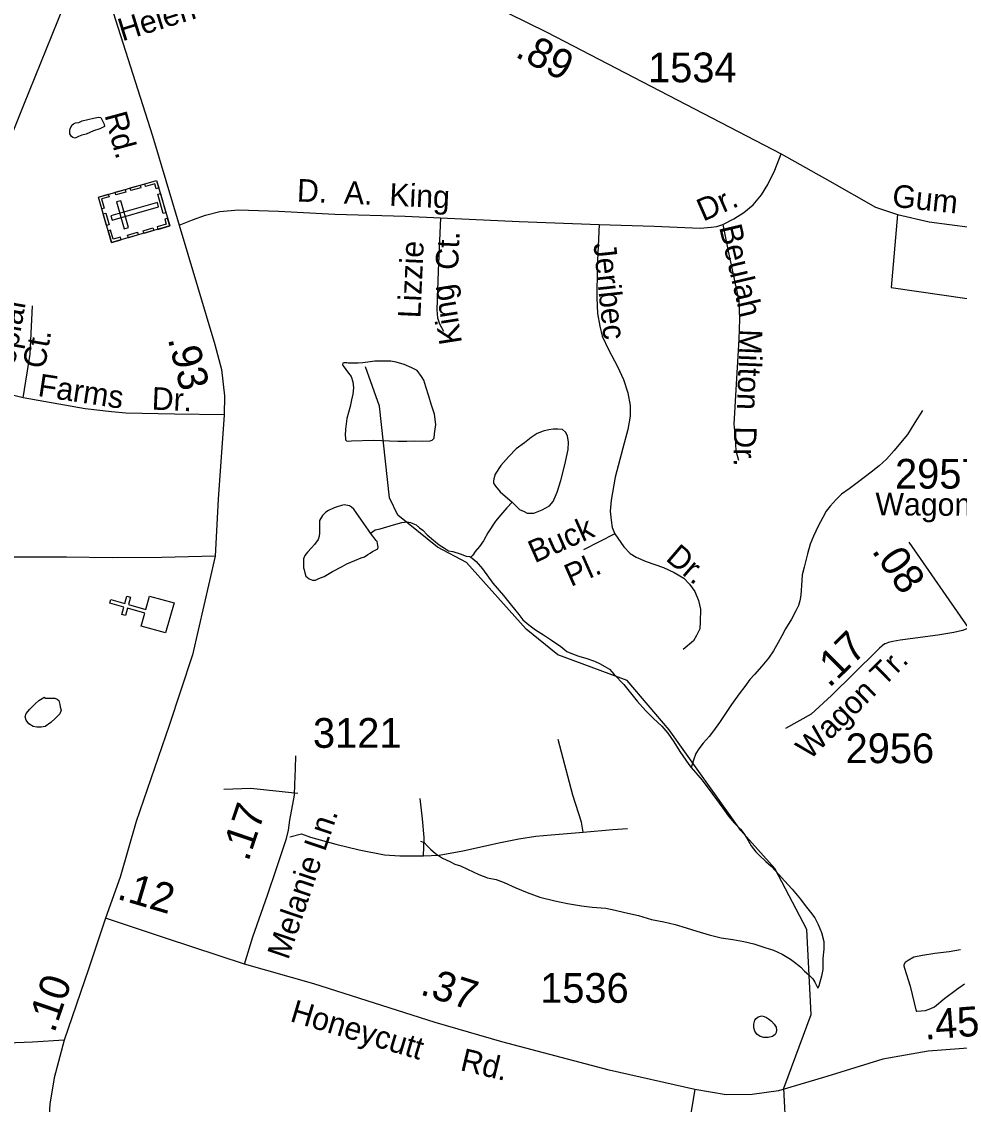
# Model space of a CAD drawing. Extents: x 2082433 to 2279600, y 546599 to 755198.
# Drawn here: x 2109763 to 2113702, y 651011 to 655560 of the extents above; entities that cross this region are included whole.
import ezdxf

# ---------------------------------------------------------------- set-up
doc = ezdxf.new("R2010")
doc.units = 0
for name, color, linetype in [('Exist Cultural Cemetery CELL', 7, 'Continuous'), ('Exist Cultural Church CELL', 7, 'Continuous'), ('Exist Hydrographic Misc Water Feature', 7, 'Continuous'), ('Exist Road Non-System Type 51', 7, 'Continuous'), ('Exist Road Non-System Type 51 Label', 7, 'Continuous'), ('Exist Road Secondary Mileage Hundredths English Label', 7, 'Continuous'), ('Exist Road Secondary Type 51 Attributed', 7, 'Continuous'), ('Exist Road Secondary Type 51 Label', 7, 'Continuous'), ('Exist Road Secondary Type 51 Number Label', 7, 'Continuous'), ('Exist Utilities Electrical Transmission Line', 7, 'Continuous')]:
    doc.layers.add(name, color=color, linetype=linetype)

msp = doc.modelspace()

# ---------------------------------------------------------------- linework, layer by layer
at = {"layer": 'Exist Cultural Cemetery CELL'}
for points in [[(2110140.2, 654631.6), (2110085.5, 654823), (2110330.3, 654893), (2110385, 654701.6)], [(2110264, 654862.2), (2110222.3, 654850.3), (2110219.2, 654861.2), (2110260.8, 654873.1)], [(2110339.4, 654861.1), (2110328.4, 654858), (2110322.3, 654879.1), (2110283.5, 654868), (2110280.4, 654878.7), (2110330.3, 654893)], [(2110127.2, 654835), (2110130.3, 654824), (2110099.3, 654815.2), (2110110.5, 654776.2), (2110099.8, 654773.1), (2110085.5, 654823)], [(2110200.6, 654844.1), (2110158.9, 654832.2), (2110155.8, 654843.1), (2110197.4, 654855)], [(2110358.2, 654753.6), (2110334.9, 654835.2), (2110345.8, 654838.4), (2110369.2, 654756.8)], [(2110138.4, 654744.4), (2110143.6, 654726.5), (2110338.5, 654782.2), (2110333.4, 654800.2)], [(2110194.4, 654689.5), (2110212.4, 654694.6), (2110180, 654807.8), (2110162.1, 654802.7)], [(2110119.9, 654702.8), (2110105.6, 654752.6), (2110116.6, 654755.7), (2110130.8, 654705.9)], [(2110375.9, 654733.3), (2110364.9, 654730.2), (2110370.9, 654709), (2110332.1, 654697.9), (2110335.1, 654687.2), (2110385, 654701.5)], [(2110181.9, 654643.5), (2110178.8, 654654.4), (2110147.8, 654645.5), (2110136.7, 654684.5), (2110126, 654681.5), (2110140.2, 654631.6)], [(2110253.2, 654663.8), (2110211.5, 654651.9), (2110208.4, 654662.9), (2110250, 654674.8)], [(2110317.8, 654682.3), (2110276.2, 654670.4), (2110273, 654681.3), (2110314.7, 654693.2)]]:
    msp.add_lwpolyline(points, close=True, dxfattribs=at)
at = {"layer": 'Exist Cultural Church CELL'}
msp.add_lwpolyline([(2110265.6, 653020.4), (2110280.8, 653075.2), (2110207.4, 653095.7), (2110198.8, 653064.9), (2110183.4, 653069.2), (2110192, 653100), (2110134.1, 653116.2), (2110138.4, 653131.6), (2110196.4, 653115.5), (2110205, 653146.3), (2110220.3, 653142), (2110211.7, 653111.2), (2110285.1, 653090.7), (2110300.7, 653146.2), (2110403.2, 653117.6), (2110368.1, 652991.8)], close=True, dxfattribs=at)
at = {"layer": 'Exist Hydrographic Misc Water Feature'}
for points in [[(2110017.9, 655143.2), (2110065.7, 655155), (2110085.6, 655159.3), (2110095.4, 655157.4), (2110099.7, 655149.5), (2110105.7, 655137.2), (2110110, 655129.3), (2110111.6, 655119.3), (2110091.7, 655109.3), (2110065.7, 655101.1), (2110034.1, 655087.2), (2110016.1, 655083.1), (2110001.7, 655077.1), (2109988, 655071.1), (2109977.7, 655073), (2109972, 655077.1), (2109966, 655089), (2109966.3, 655100.7), (2109967.5, 655111.1), (2109975.7, 655126.8), (2109981.4, 655130.8), (2109989.8, 655134.9), (2110003.8, 655136.8), (2110017.9, 655143.2)], [(2111343.4, 653797.6), (2111349.3, 653797.5), (2111381.7, 653797.9), (2111415.4, 653798.1), (2111445.5, 653798), (2111479.5, 653798.1), (2111487.3, 653802.2), (2111495.5, 653810.2), (2111497.2, 653828.2), (2111503.1, 653867.9), (2111497.4, 653910.1), (2111483, 653952.1), (2111473, 653986), (2111460.5, 654026), (2111452.9, 654054), (2111442.6, 654069.7), (2111424.6, 654093.9), (2111402.4, 654105.8), (2111370.2, 654119.6), (2111336.2, 654129.6), (2111314.3, 654133.3), (2111246.4, 654133.1), (2111226.5, 654131.2), (2111196.4, 654126.9), (2111176.5, 654125), (2111172.2, 654124.8), (2111160.3, 654125), (2111144.7, 654125), (2111134.4, 654124.9), (2111128.5, 654127), (2111124.6, 654126.8), (2111120.7, 654126.6), (2111116.4, 654126.8), (2111112.3, 654125), (2111110.4, 654118.8), (2111112.7, 654114.8), (2111118.4, 654108.6), (2111132.6, 654088.7), (2111146.7, 654069.1), (2111154.5, 654046.8), (2111157, 654020.8), (2111154.7, 653994.9), (2111149.2, 653971), (2111143.3, 653943.1), (2111128.9, 653892.9), (2111123.4, 653847.1), (2111121.5, 653821), (2111123.4, 653811), (2111123.4, 653802.9), (2111127.7, 653799), (2111135.9, 653796.9), (2111149.4, 653799), (2111239.4, 653801.1), (2111343.4, 653797.6)], [(2111631.8, 653287.6), (2111509.8, 653352.3), (2111342.9, 653486.9), (2111308.9, 653559.8), (2111266, 653944.4), (2111208, 654109.6)], [(2113547.1, 653926.4), (2113515.3, 653876), (2113483.5, 653826), (2113455.4, 653789.8), (2113427.5, 653757.9), (2113396, 653721.7), (2113365.8, 653693.4), (2113332.2, 653667.3), (2113278.3, 653627.1), (2113238.5, 653597.1), (2113206.7, 653574.8), (2113184.8, 653552.9), (2113158.7, 653524.8), (2113142.7, 653502.5), (2113129, 653476.5), (2113109.5, 653440.6), (2113089.2, 653398.2), (2113075.5, 653364.2), (2113063.8, 653324.2), (2113050.2, 653268.3), (2113042.2, 653236.2), (2113040.4, 653212.2), (2113036.5, 653150.3), (2113032.4, 653126.2), (2113026.7, 653106.4), (2113014.8, 653084.2), (2112996.7, 653050), (2112971.1, 653008.1), (2112956.9, 652979.8), (2112941.4, 652951.8), (2112921.7, 652915.8), (2112899.7, 652885.9), (2112871.8, 652851.5), (2112842.1, 652817.6), (2112822.2, 652795.4), (2112800.5, 652767.1), (2112776.5, 652735), (2112744.9, 652691.1), (2112722.6, 652656.8), (2112694.7, 652614.8), (2112669, 652580.9), (2112651, 652556.9), (2112625.6, 652528.7), (2112607.5, 652504.6), (2112595.6, 652484.5), (2112585.4, 652456.5), (2112579.4, 652438.3), (2112575.7, 652426.3)], [(2111823.4, 653540.8), (2111855, 653510.8), (2111873.4, 653501.2), (2111887.2, 653495), (2111915.3, 653495.2), (2111949.1, 653509.2), (2111981.1, 653525.4), (2111995.2, 653543.6), (2112012.9, 653583.5), (2112028.7, 653631.8), (2112044.7, 653697.5), (2112058.2, 653761.6), (2112060.2, 653793.7), (2112055.9, 653819.5), (2112047.7, 653835.7), (2112035.6, 653845.7), (2112015.5, 653847.5), (2111995.7, 653847.3), (2111977.4, 653845.2), (2111953.6, 653839.5), (2111928, 653829.1), (2111904, 653812.9), (2111875.7, 653790.8), (2111840.4, 653764.9), (2111810.3, 653732.5), (2111776.5, 653694.7), (2111752.5, 653658.6), (2111746.5, 653638.4), (2111744.5, 653628.6), (2111744.7, 653624.5), (2111744.9, 653620.4), (2111753.1, 653608.2), (2111773, 653584.5), (2111823.4, 653540.8)], [(2111823.4, 653540.8), (2111801.1, 653516.6), (2111775.6, 653488.4), (2111753.5, 653460.5), (2111721.7, 653412.2), (2111703.7, 653378.4), (2111686, 653354.3), (2111668.4, 653334.3), (2111657.9, 653318), (2111650.3, 653310.2)], [(2111229, 653411.4), (2111220.6, 653423.2), (2111190.6, 653465), (2111168.5, 653497.2), (2111158.4, 653511.2), (2111148.2, 653519.3), (2111140.2, 653524.9), (2111118.4, 653529.1), (2111106.1, 653526.9), (2111088.7, 653521), (2111076.4, 653516.8), (2111052.2, 653506.6), (2111040.7, 653498.6), (2111026.8, 653484.5), (2111014.7, 653464.5), (2111014.9, 653450.6), (2111014.9, 653440.5), (2111014.7, 653426.8), (2111014.5, 653410.6), (2111013, 653398.6), (2111008.9, 653384.6), (2110992.9, 653362.7), (2110980.9, 653348.7), (2110963.4, 653330.7), (2110953, 653316.4), (2110947.2, 653302.3), (2110947.2, 653294.6), (2110947.2, 653282.4), (2110947.2, 653264.6), (2110949.3, 653256.6), (2110953.4, 653244.6), (2110957.3, 653230.6), (2110963.6, 653224.4), (2110971.4, 653218.7), (2110985.4, 653212.6), (2110997.3, 653212.8), (2111011.4, 653220.8), (2111033.5, 653228.8), (2111069.2, 653249), (2111109, 653270.9), (2111129.1, 653281.3), (2111163.1, 653295.2), (2111189, 653307.5), (2111203.3, 653311.4), (2111216.9, 653321.1), (2111226.7, 653327.3), (2111237.2, 653333.5), (2111245, 653337.5), (2111258.7, 653345.6), (2111261, 653351.4), (2111258.9, 653359.4), (2111256.9, 653375.5), (2111253, 653379.3), (2111229, 653411.4)], [(2111229, 653411.4), (2111248.6, 653425.4), (2111268.9, 653429.6), (2111296.6, 653437.6), (2111324.7, 653445.5), (2111360.8, 653455.9), (2111382.3, 653457.9), (2111396.5, 653455.7), (2111406.9, 653451.7)], [(2111406.9, 653451.7), (2111420.9, 653446), (2111434.4, 653433.8), (2111448.6, 653423.9), (2111466.6, 653404.2), (2111492.7, 653382), (2111516.9, 653362.1), (2111538.8, 653348.2), (2111556.8, 653336.5), (2111574.7, 653334.2), (2111604.6, 653324.5), (2111630, 653314.1)], [(2111630, 653314.1), (2111646.2, 653312.1), (2111650.3, 653310.2)], [(2111650.3, 653310.2), (2111655.9, 653306.1), (2111672.3, 653292.3), (2111698.5, 653260.4), (2111742.4, 653200.6), (2111786.9, 653148.8), (2111820.7, 653106.8), (2111833, 653091.1), (2111851.1, 653068.9), (2111869.1, 653047.2), (2111893.5, 653025.2), (2111921.6, 653005.1), (2111955.5, 652983.4), (2111989.5, 652961.6), (2112027.4, 652934), (2112053.9, 652914.1), (2112083.8, 652900.3), (2112103.7, 652894), (2112137.8, 652884.4), (2112169.9, 652872.7), (2112189.8, 652862.7), (2112212.2, 652850.9), (2112232.3, 652838.9), (2112252.4, 652816.8), (2112292.6, 652775), (2112349, 652705.2), (2112383.2, 652665.6), (2112417, 652631.6), (2112452.9, 652599.8), (2112477.3, 652569.8), (2112503.2, 652534.2), (2112527.6, 652494), (2112565.9, 652438.4), (2112575.7, 652426.3)], [(2113462.9, 649540), (2113486.9, 649782.3), (2113460.8, 649881.2), (2113309.7, 650205.8), (2113183.8, 650405.1), (2113149.8, 650586.2), (2112973.9, 650888.4), (2112964.8, 651078.8), (2113079.9, 651388.1), (2113061.8, 651746.1), (2112926.9, 652001.4), (2112784.8, 652161.8), (2112483, 652584.5), (2112306.9, 652791.5), (2112014.9, 652899.2), (2111882, 653006.8), (2111631.8, 653287.6)], [(2109857.2, 652721.5), (2109863.1, 652717.3), (2109883.2, 652717.5), (2109903.1, 652717.3), (2109913.1, 652713.4), (2109918.9, 652707.6), (2109923.4, 652691.5), (2109925.7, 652681.5), (2109929.3, 652667.6), (2109923.6, 652651.4), (2109905.4, 652633.5), (2109885.7, 652615.4), (2109861.7, 652599.1), (2109845.9, 652595.4), (2109827.6, 652595.4), (2109811.6, 652599), (2109793.6, 652609), (2109781.9, 652625), (2109777.4, 652639.1), (2109781.5, 652653), (2109797.7, 652671.2), (2109819.6, 652693.1), (2109835.6, 652707.3), (2109849.2, 652715.4), (2109857.2, 652721.5)], [(2112575.7, 652426.3), (2112622.1, 652372.7), (2112666.2, 652312.9), (2112708.2, 652255), (2112732.4, 652221.3), (2112756.6, 652193.3), (2112783.1, 652167.4), (2112797, 652149.5), (2112808.9, 652129.4), (2112826.9, 652097.5), (2112847.4, 652071.7), (2112861.2, 652057.8), (2112889.5, 652031.6), (2112911.4, 652012.1), (2112931.5, 651990), (2112967.8, 651950.4), (2113000, 651914.3), (2113034.4, 651872.6), (2113054.1, 651846.5), (2113076.5, 651818.8), (2113094.5, 651795), (2113108.5, 651766.9), (2113122.4, 651733.2), (2113132.7, 651695.1), (2113132.9, 651663.1), (2113129.2, 651623.1), (2113129.2, 651577.2), (2113123.2, 651548.9), (2113112, 651508.9), (2113107.7, 651499)], [(2111438.5, 652116.2), (2111454.5, 652110.6), (2111466.6, 652096.6), (2111481, 652082.6), (2111500.9, 652064.6), (2111531.2, 652044.6), (2111561.1, 652030.8), (2111582.9, 652020.6), (2111606.1, 652012.6), (2111636, 651998.3)], [(2111636, 651998.3), (2111684, 651976.5), (2111720.3, 651962.8), (2111756.4, 651954.9), (2111790, 651943), (2111838.4, 651921.1), (2111886.6, 651901.6), (2111940.5, 651881.7), (2112002.6, 651866.2), (2112056.3, 651854.4), (2112114.6, 651844.4), (2112160.3, 651838.7), (2112216.7, 651835), (2112256.7, 651827.3), (2112296.7, 651817.2), (2112354.7, 651803.6), (2112408.6, 651787.7), (2112460.5, 651778.2), (2112508.7, 651766.5), (2112554.4, 651752.6), (2112598.9, 651738.6), (2112651.2, 651723), (2112701, 651711), (2112750.7, 651703.5), (2112797, 651695.7), (2112838.6, 651685.7), (2112885, 651670.1), (2112921.3, 651658.2), (2112957.3, 651642.2), (2112993.2, 651620.5), (2113015.2, 651604.6), (2113035.5, 651586.5), (2113051.7, 651570.7), (2113069.3, 651554.6), (2113085.9, 651538.7), (2113095.3, 651524.7), (2113107.7, 651499)], [(2113707, 651659.7), (2113658.8, 651651.6), (2113599.2, 651645.2), (2113546.9, 651636.9), (2113511, 651628.9), (2113487.4, 651614.7), (2113474.9, 651606.4), (2113469, 651596.4), (2113469.4, 651592.7), (2113471.4, 651582.6), (2113495.8, 651506.7)], [(2113495.8, 651506.7), (2113520, 651402.8), (2113523.9, 651402.7), (2113560, 651404.9), (2113581.7, 651413), (2113597.9, 651421.1), (2113641.4, 651457.5), (2113689.6, 651493.6), (2113723.2, 651517.7)], [(2112912.4, 651360.2), (2112924.5, 651348.3), (2112932.3, 651334.5), (2112934.6, 651322.4), (2112932.9, 651312.5), (2112928.6, 651304.2), (2112916.5, 651296.3), (2112898.5, 651292.1), (2112880.7, 651292), (2112864.7, 651296), (2112850.7, 651305.9), (2112842.9, 651318), (2112838.8, 651332), (2112838.6, 651347.8), (2112842.5, 651363.9), (2112848.5, 651371.9), (2112856.3, 651378), (2112872.3, 651382.1), (2112882.1, 651380.2), (2112892.6, 651376.2), (2112900.5, 651370.1), (2112912.4, 651360.2)]]:
    msp.add_lwpolyline(points, dxfattribs=at)
at = {"layer": 'Exist Road Non-System Type 51'}
for p, q in [((2113441.8, 654749.4), (2113415.8, 654442.6)), ((2113415.8, 654442.6), (2113734.3, 654397.1)), ((2112255.4, 653408), (2112123.7, 653341.3))]:
    msp.add_line(p, q, dxfattribs=at)
for points in [[(2112708.7, 654707.9), (2112754, 654731), (2112796.7, 654758.4), (2112836.1, 654790.9), (2112870.3, 654831.9), (2112897.7, 654876.4), (2112926.7, 654936.3), (2112954.1, 655004.7)], [(2110424.8, 654705.1), (2110480.8, 654727.6), (2110535.5, 654746.4), (2110595.4, 654761.8), (2110674, 654768.7), (2110841.7, 654763.5), (2111079.4, 654751.6), (2111373.6, 654743), (2111522.4, 654736.2)], [(2111522.4, 654736.2), (2111512.2, 654512.1), (2111507, 654349.6), (2111509.6, 654316.2), (2111518.2, 654290.6), (2111535.3, 654259.8)], [(2111522.4, 654736.2), (2111852.6, 654720.8), (2112189.5, 654707.1)], [(2112189.5, 654707.1), (2112181, 654525.8), (2112179.3, 654399.2), (2112182.7, 654334.2), (2112191.2, 654281.2), (2112201.5, 654238.4), (2112228.9, 654182), (2112265.6, 654111), (2112291.3, 654056.2), (2112310.1, 653999.8), (2112318.7, 653946.8), (2112318.7, 653902.3), (2112310.1, 653845.9), (2112287.9, 653767.2), (2112256.2, 653646.6), (2112239.1, 653549.1), (2112235.7, 653502.9), (2112239.1, 653465.3), (2112244.3, 653434.5), (2112255.4, 653408)], [(2112189.5, 654707.1), (2112419.6, 654701.1), (2112612.9, 654692.5), (2112659, 654696), (2112683, 654699.4), (2112708.7, 654707.9)], [(2112708.7, 654707.9), (2112730.9, 654595), (2112775.4, 654386.4), (2112778.8, 654309.4), (2112775.4, 654225.6), (2112762.5, 654012.6), (2112754, 653868.9), (2112760, 653813.4), (2112763.4, 653756.9), (2112773.6, 653717.6)], [(2109769.3, 653980), (2109644.7, 654009.9), (2109586.3, 654025.2), (2109540.3, 654046.1), (2109461, 654104.5), (2109353.8, 654203.3), (2109264, 654288.9), (2109194.4, 654357.1), (2109134.6, 654393.3), (2109078.9, 654417), (2108998.2, 654429.5)], [(2109769.3, 653980), (2109799.2, 654163), (2109808.9, 654366.2)], [(2110613.4, 653908.3), (2110404.7, 653911.1), (2110201.4, 653915.2), (2110140.9, 653920.1), (2110029.6, 653932.6), (2109769.3, 653980)], [(2112255.4, 653408), (2112293, 653353.2), (2112318.7, 653325.9), (2112344.3, 653310.5), (2112387.1, 653291.7), (2112458.9, 653266), (2112503.4, 653245.5), (2112544.4, 653221.5), (2112568.4, 653195.9), (2112590.6, 653165.1), (2112606, 653127.5), (2112614.6, 653091.5), (2112613.7, 653037.7), (2112612, 653008.6), (2112598.3, 652981.2), (2112584.6, 652959), (2112541.9, 652921.3)], [(2110576.5, 653314.7), (2110351.8, 653308.4), (2110143, 653307), (2109952.3, 653309.8), (2109580.5, 653309.8)], [(2112121.6, 652154.3), (2112115.2, 652196.9), (2112079, 652309.8), (2112017.2, 652544.1)], [(2110923.3, 652317.2), (2110725.2, 652338.5), (2110612.3, 652334.3)], [(2111451.6, 652055.2), (2111453.8, 652131.9), (2111447.4, 652210.7), (2111436.7, 652295.9)], [(2110890.3, 652135.1), (2110938.2, 652146.8), (2110976.6, 652134), (2111083.1, 652104.2), (2111181.1, 652080.8), (2111287.6, 652059.5), (2111351.5, 652055.2), (2111451.6, 652055.2)], [(2111451.6, 652055.2), (2111516.6, 652058.4), (2111616.7, 652075.4), (2111774.4, 652111.6), (2111851.1, 652126.6), (2111923.5, 652137.2), (2111987.4, 652143.6), (2112121.6, 652154.3)], [(2112121.6, 652154.3), (2112246.2, 652166), (2112308, 652170.2)]]:
    msp.add_lwpolyline(points, dxfattribs=at)
at = {"layer": 'Exist Road Secondary Type 51 Attributed'}
msp.add_line((2113741.9, 653011.7), (2113491.7, 653372.4), dxfattribs=at)
for points in [[(2109871.6, 656520.8), (2109962.7, 656213.9), (2110042.8, 655934.8), (2110147.9, 655598.7), (2110313.5, 655080.9), (2110424.8, 654705.1), (2110575.2, 654204), (2110603, 654098.3), (2110614.8, 653987.6), (2110613.4, 653908.3), (2110589.1, 653554), (2110576.5, 653314.7), (2110481.2, 652899.2), (2110382.2, 652602), (2110244.5, 652199.2), (2110176.9, 651965.1), (2110115.1, 651793.5)], [(2110852, 656403), (2110894.9, 656330.6), (2110969.7, 656200), (2111079.5, 656056.7), (2111190.9, 655953.2), (2111318.2, 655856.1), (2111564.1, 655715.9), (2111969.8, 655515.3), (2112954.1, 655004.7), (2113157.6, 654890.1), (2113349.2, 654780.6), (2113441.8, 654749.4), (2113575, 654719.1), (2113746, 654696.1)], [(2113741.9, 653011.7), (2113740.8, 653011.3), (2113715.1, 653002.1), (2113678.6, 652993.4), (2113612.2, 652982.8), (2113453.1, 652961.8), (2113421.9, 652955.2), (2113404.3, 652951.1), (2113390.4, 652945.5), (2113389.5, 652945.1), (2113378.9, 652938.6), (2113376.4, 652936.6), (2113366.9, 652927.9), (2113355, 652916.2), (2113165.4, 652728.5), (2113079.4, 652650.3), (2112971.3, 652589.4)], [(2110699, 651599.6), (2110733.6, 651714.4), (2110795.4, 651889.1), (2110833.7, 652002), (2110876.3, 652127.6), (2110883.9, 652162.4), (2110890.2, 652205), (2110909.3, 652309.8), (2110910.3, 652355), (2110913.9, 652421.9), (2110915.6, 652474.8)], [(2110115.1, 651793.5), (2110044, 651578.1), (2109941.9, 651279.8)], [(2110699, 651599.6), (2110371, 651707.9), (2110115.1, 651793.5)], [(2112590.3, 651073.3), (2112231.3, 651154.1), (2111779.7, 651273.4), (2111500, 651354.4), (2110990, 651516.8), (2110699, 651599.6)], [(2109941.9, 651279.8), (2109809.5, 651272.7), (2109453.8, 651258.1), (2109138.9, 651232.8), (2108950.9, 651207.4), (2108776.9, 651149), (2108653.7, 651078.7), (2108553.5, 650995.2), (2108483.2, 650923.4), (2108434.3, 650882.6), (2108402, 650843), (2108382.1, 650814.1)], [(2109941.9, 651279.8), (2109900.4, 651122.7), (2109881.3, 651011.2), (2109870.2, 650837.7), (2109845.5, 650301), (2109819.2, 649734.2), (2109807.3, 649503.3)], [(2114914.8, 651272.2), (2114598.6, 651272.4), (2114156.2, 651270.8), (2113831.6, 651253.3), (2113571.4, 651234.2), (2113380.5, 651200.7), (2113145, 651127.5), (2112942.9, 651067), (2112832.3, 651052.6), (2112722.5, 651051.1), (2112590.3, 651073.3)], [(2112590.3, 651073.3), (2112518.4, 650639.4)]]:
    msp.add_lwpolyline(points, dxfattribs=at)
at = {"layer": 'Exist Utilities Electrical Transmission Line'}
msp.add_lwpolyline([(2105878, 645721.2), (2106048.8, 646131.7), (2106203.4, 646526.2), (2106376.1, 646944.4), (2106578.5, 647427.1), (2106721.4, 647785.4), (2106925.9, 648272), (2107102.4, 648710.3), (2107334.6, 649276.8), (2107543, 649797.3), (2107721.7, 650227.9), (2107894.3, 650638.3), (2108053, 651036.7), (2108231.7, 651467), (2108360.7, 651779.4), (2108442, 651983.7), (2108717.9, 652646.3), (2108914.3, 653118.8), (2109130.9, 653635.4), (2109331.2, 654145.9), (2109533.6, 654616.3), (2109771.7, 655210.9), (2110009.9, 655799.6)], dxfattribs=at)

# ---------------------------------------------------------------- texts
at = {"layer": 'Exist Road Non-System Type 51 Label'}
for s, rotation, p in [('Helen', 17.2479, (2110185.8, 655477)), ('D.  A.  King', 357.3556, (2110918.2, 654804.8)), ('Dr.', 23.6444, (2112625.9, 654719.1)), ('Beulah', 283.2103, (2112692.4, 654696.9)), ('Lizzie', 87.4381, (2111438, 654312.6)), ('Ct.', 87.4381, (2111596.1, 654515.1)), ('Jeribec', 276.1111, (2112164.7, 654627.3)), ('King', 98.9118, (2111613.3, 654210.6)), ('Poplar', 79.974, (2109719.2, 654030.4)), ('Ct.', 79.974, (2109860.1, 654098)), ('Milton', 267.7804, (2112780.5, 654269)), ('Farms', 351.3414, (2109827.9, 653987.3)), ('Dr.', 357.4733, (2110308.2, 653930.1)), ('Dr.', 269.2321, (2112755.5, 653859.9)), ('Buck', 23.9777, (2111918, 653283.8)), ('Dr.', 319.3785, (2112464.3, 653299.7)), ('Pl.', 23.9777, (2112070.2, 653184.2))]:
    msp.add_text(s, height=95, rotation=rotation, dxfattribs=at).set_placement(p)
at = {"layer": 'Exist Road Secondary Mileage Hundredths English Label'}
for s, rotation, p in [('.89', 332.582, (2111831.6, 655414.9)), ('.93', 283.6975, (2110376.9, 654227.6)), ('.08', 304.7552, (2113330.9, 653336.2)), ('.17', 44.7034, (2113155.5, 652757.7)), ('.17', 71.2414, (2110715, 652027.4)), ('.12', 343.5593, (2110159.5, 651875.3)), ('.10', 71.2877, (2109900.4, 651307.5)), ('.37', 342.3344, (2111432.6, 651474)), ('.45', 4.2006, (2113557.7, 651282.5))]:
    msp.add_text(s, height=125, rotation=rotation, dxfattribs=at).set_placement(p)
at = {"layer": 'Exist Road Secondary Type 51 Label'}
for s, rotation, p in [('Rd.', 285.1729, (2110110.6, 655167.7)), ('Gum', 353.9138, (2113416.8, 654782.8)), ('Wagon Tr.', 359.6909, (2113349.3, 653485.7)), ('Wagon Tr.', 44.7034, (2113072.9, 652454.7)), ('Melanie Ln.', 71.2413, (2110882.6, 651614.9)), ('Honeycutt', 343.3532, (2110886.4, 651361.1)), ('Rd.', 346.5823, (2111601.4, 651155.1))]:
    msp.add_text(s, height=95, rotation=rotation, dxfattribs=at).set_placement(p)
at = {"layer": 'Exist Road Secondary Type 51 Number Label'}
for s, p in [('1534', (2112394.4, 655305.3)), ('2957', (2113431.8, 653597.8)), ('3121', (2110986.9, 652508.8)), ('2956', (2113224.1, 652444.4)), ('1536', (2111941.2, 651437.5))]:
    msp.add_text(s, height=125, dxfattribs=at).set_placement(p)

doc.saveas('drawing.dxf')
